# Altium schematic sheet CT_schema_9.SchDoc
size 274 x 160 mm
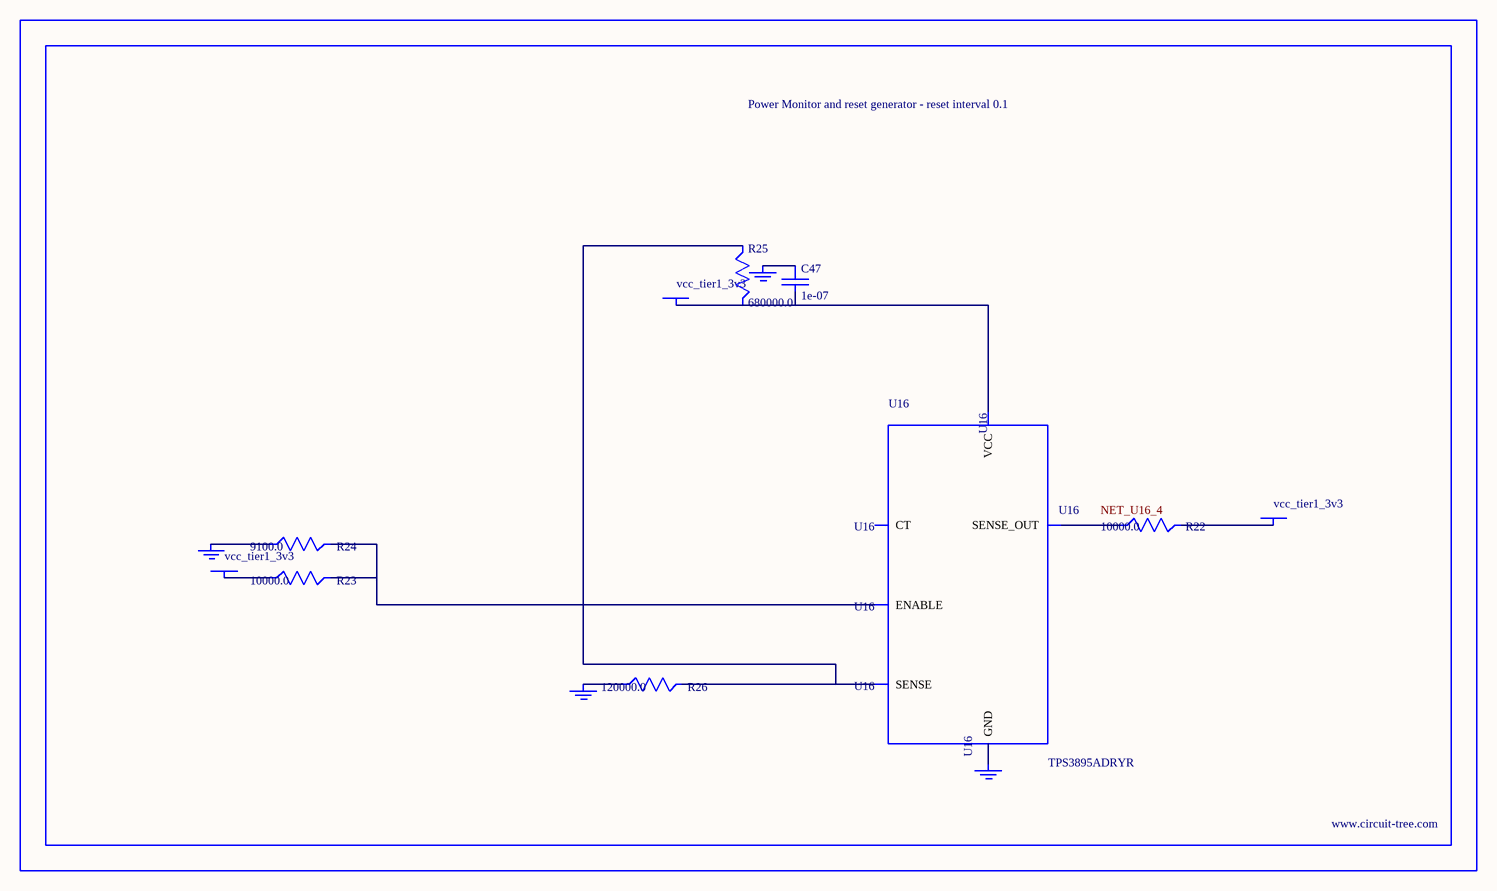
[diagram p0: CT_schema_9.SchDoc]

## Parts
BORDER8  (no value)
C47  1e-07  [C0402]
GND_INSTANCE_8_0  (no value)
GND_INSTANCE_8_1  (no value)
GND_INSTANCE_8_2  (no value)
GND_INSTANCE_8_3  (no value)
POWER_INSTANCE_8_0  vcc_tier1_3v3
POWER_INSTANCE_8_1  vcc_tier1_3v3
POWER_INSTANCE_8_2  vcc_tier1_3v3
R22  10000.0  [R0603]
R23  10000.0  [R0603]
R24  9100.0  [R0603]
R25  680000.0  [R0603]
R26  120000.0  [R0603]
U16  TPS3895ADRYR  [SON-6]

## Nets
NetC47_1: C47.1 GND_INSTANCE_8_2.0(GND)
NetC47_2: C47.2 POWER_INSTANCE_8_2.0(PWR) R25.2 U16.6(VCC)
NetGND_INSTANCE_8_0_0: GND_INSTANCE_8_0.0(GND) R24.1
NetGND_INSTANCE_8_1_0: GND_INSTANCE_8_1.0(GND) R26.1
NetGND_INSTANCE_8_3_0: GND_INSTANCE_8_3.0(GND) U16.2(GND)
NetPOWER_INSTANCE_8_0_0: POWER_INSTANCE_8_0.0(PWR) R23.1
NetPOWER_INSTANCE_8_1_0: POWER_INSTANCE_8_1.0(PWR) R22.2
NetR22_1: R22.1 U16.4(SENSE_OUT)
NetR23_2: R23.2 R24.2 U16.1(ENABLE)
NetR25_1: R25.1 R26.2 U16.3(SENSE)

Not connected (* = marked no-connect by the designer): U16 5(CT)

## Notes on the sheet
- Labels drawn without touching a wire or pin: NET_U16_4

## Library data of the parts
BORDER8 = BORDER_PAGE8
C47 = C0402C104K3RACTU
GND_INSTANCE_8_0-GND_INSTANCE_8_3 = GND
POWER_INSTANCE_8_0-POWER_INSTANCE_8_2 = PWR
R22 R23 = RC0603JR-0710KL
R24 = RC0603JR-079K1L
R25 = RC0603JR-07680KL
R26 = RC0603JR-07120KL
